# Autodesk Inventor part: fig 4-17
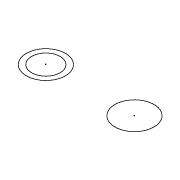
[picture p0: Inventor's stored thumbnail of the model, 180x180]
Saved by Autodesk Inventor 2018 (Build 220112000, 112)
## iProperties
Created: 2005-02
Part Number: fig 4-17
Document SubType Name: Modeling
Designer: CADCIM
Manufacturer: Standard
Standards Organization: Custom
Density: 1 g/cm^3
Material: Generic
Appearance: Default
Author: CADCIM
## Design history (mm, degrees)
sketch "Sketch1"
  geometry: C1 r 7.935 at (-23.563, 7.599); C2 r 7.935 at (12.452, 7.599); C3 r 5.782 at (-23.563, 7.599)
  constraints: 3 centre point, 1 coincident, 1 equal radius, 1 other
